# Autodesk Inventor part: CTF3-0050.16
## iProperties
Shininess: 64.0
Length Units: 11269
Angle Units: 11279
Time Units: 11290
Mass Units: 11283
Length Display Precision: 3
Angle Display Precision: 2
Compacted: True
Part Number: CTF3-0050.16
Document SubType Name: Modeling
Created: 2004-01
Designer: Lollo
Density: 0.0
Volumn: 0.0
Area: 0.0
PropertySet Name: Model Information
Control State: 0
Master: False
Checked Out: False
Author: Lollo
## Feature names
1. Estrusione1 [Extrusion]
2. Smusso2 [Chamfer]
3. Smusso5 [Chamfer]
4. Foro1 [Hole]
